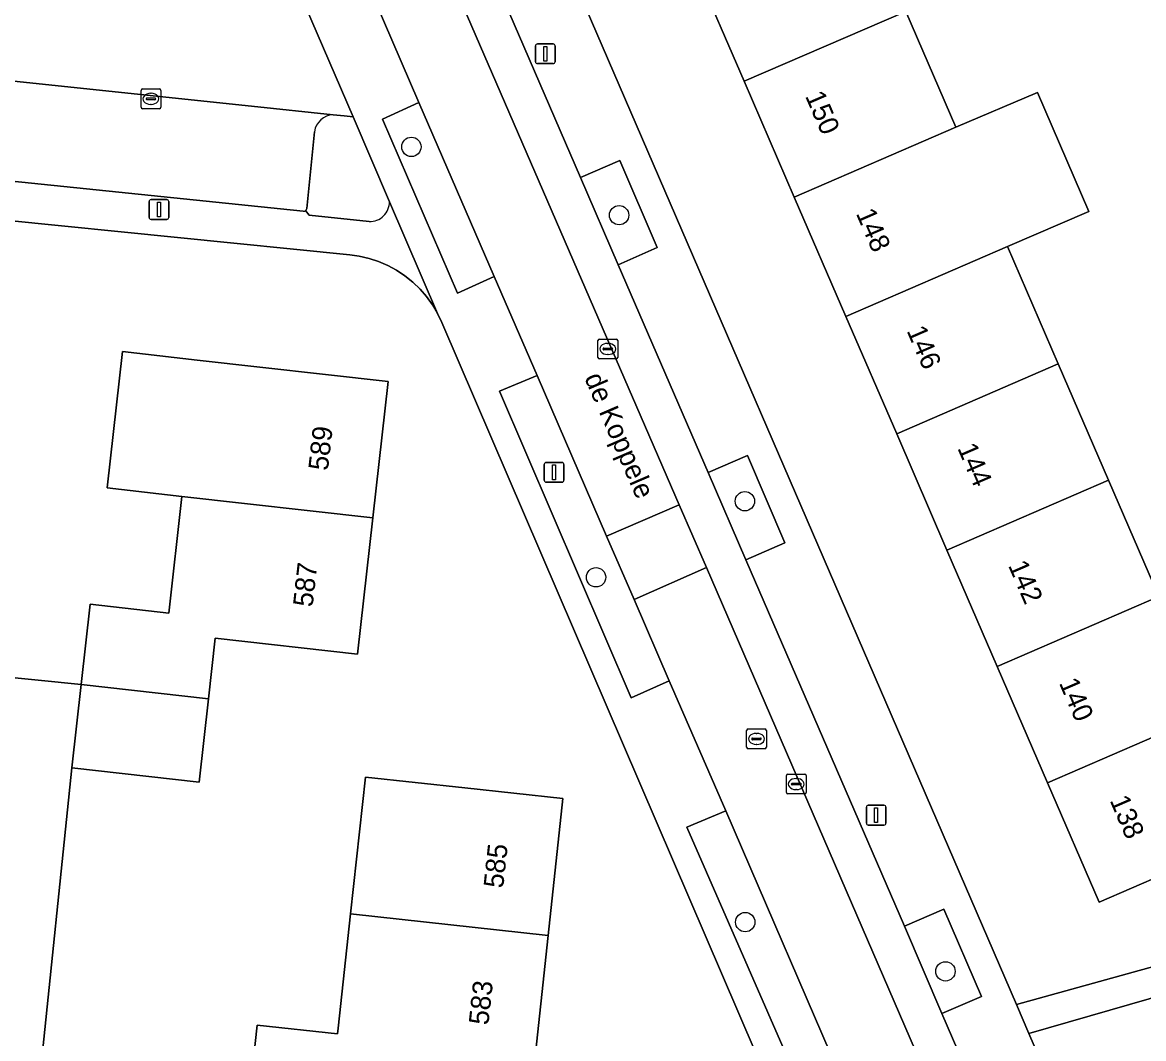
# Model space of a CAD drawing. Extents: x 162026 to 163502, y 387295 to 388169.
# Drawn here: x 162199.2 to 162255.9, y 388022.7 to 388074.1 of the extents above; entities that cross this region are included whole.
import ezdxf

# ---------------------------------------------------------------- set-up
doc = ezdxf.new("R2010")
doc.units = 0
for name, color, linetype in [('IMGEO_Boom', 7, 'Continuous'), ('IMGEO_Erf', 7, 'Continuous'), ('IMGEO_Groenvoorziening', 7, 'Continuous'), ('IMGEO_Kolk', 7, 'Continuous'), ('IMGEO_Lichtmast', 7, 'Continuous'), ('IMGEO_Openbare_ruimte_label', 7, 'Continuous'), ('IMGEO_Pand', 7, 'Continuous'), ('IMGEO_Pand_nummerreeks', 7, 'Continuous'), ('IMGEO_Parkeervlak_open', 7, 'Continuous'), ('IMGEO_Rijbaan_lokaal_open', 7, 'Continuous'), ('IMGEO_Rioolput', 7, 'Continuous'), ('IMGEO_Voetpad_open', 7, 'Continuous')]:
    doc.layers.add(name, color=color, linetype=linetype)

msp = doc.modelspace()

# ---------------------------------------------------------------- linework, layer by layer
at = {"layer": 'IMGEO_Boom'}
for centre in [(162218.858, 388067.822), (162229.36, 388064.369), (162235.718, 388049.909), (162228.193, 388046.062), (162235.737, 388028.632), (162245.86, 388026.143)]:
    msp.add_circle(centre, 0.489, dxfattribs=at)
at = {"layer": 'IMGEO_Erf'}
for points in [[(162261.522, 388091.098), (162242.55, 388093.234), (162223.34, 388084.876), (162249.447, 388024.462), (162267.947, 388029.586)], [(162261.797, 388033.179), (162253.631, 388029.647), (162251.023, 388035.676), (162248.479, 388041.559), (162245.934, 388047.442), (162243.393, 388053.317), (162240.825, 388059.254), (162238.217, 388065.284), (162235.684, 388071.141), (162233.135, 388077.032)], [(162243.851, 388074.671), (162246.384, 388068.815), (162250.512, 388070.57), (162253.108, 388064.563), (162248.992, 388062.784), (162251.561, 388056.846), (162254.101, 388050.972), (162256.646, 388045.089)], [(162240.422, 388012.373), (162220.404, 388058.948), (162220.184, 388059.405), (162219.924, 388059.841), (162219.627, 388060.251), (162219.294, 388060.634), (162218.928, 388060.985), (162218.532, 388061.302), (162218.109, 388061.583), (162217.663, 388061.824), (162217.198, 388062.025), (162216.716, 388062.184), (162216.222, 388062.298), (162215.754, 388062.365), (162198.322, 388064.111)], [(162189.1, 388041.95), (162202.158, 388040.642), (162202.615, 388044.705), (162206.59, 388044.258), (162207.253, 388050.154), (162203.476, 388050.579), (162204.252, 388057.472), (162208.028, 388057.047), (162217.681, 388055.961), (162216.906, 388049.068), (162216.131, 388042.174), (162208.945, 388042.982), (162208.601, 388039.919), (162208.126, 388035.699), (162201.684, 388036.423), (162200.063, 388020.584)], [(162210.625, 388019.406), (162211.059, 388023.421), (162215.13, 388022.981), (162215.161, 388023.267), (162215.786, 388029.043), (162216.535, 388035.96), (162221.553, 388035.417), (162226.523, 388034.879), (162225.774, 388027.96), (162225.025, 388021.039)], [(162299.337, 388025.532), (162289.611, 388026.623), (162289.188, 388022.806), (162286.544, 388023.099), (162283.9, 388023.392), (162284.323, 388027.209), (162276.998, 388028.02), (162276.575, 388024.203), (162273.921, 388024.497), (162271.278, 388024.79), (162271.7, 388028.607), (162270.784, 388028.723), (162270.329, 388028.733), (162270.019, 388028.709), (162269.435, 388028.585), (162250.08, 388022.997), (162258.662, 388003.139)]]:
    msp.add_lwpolyline(points, dxfattribs=at)
at = {"layer": 'IMGEO_Groenvoorziening'}
for points in [[(162219.235, 388070.071), (162217.398, 388069.231), (162221.184, 388060.42), (162223.047, 388061.269)], [(162227.416, 388066.277), (162229.312, 388061.864), (162231.285, 388062.729), (162229.402, 388067.141)], [(162225.214, 388056.269), (162223.313, 388055.466), (162229.974, 388039.966), (162231.893, 388040.822), (162230.114, 388044.937), (162228.73, 388048.137)], [(162233.87, 388051.368), (162235.771, 388046.953), (162237.745, 388047.801), (162235.843, 388052.217)], [(162234.759, 388034.257), (162232.785, 388033.424), (162238.987, 388019.237), (162240.871, 388020.067)], [(162245.771, 388029.279), (162243.789, 388028.432), (162245.674, 388024.015), (162247.68, 388024.879)]]:
    msp.add_lwpolyline(points, close=True, dxfattribs=at)
for points in [[(162215.914, 388069.339), (162215.452, 388069.388), (162214.899, 388069.446)], [(162217.745, 388065.052), (162215.914, 388069.339)], [(162213.961, 388068.59), (162213.574, 388064.707)], [(162201.684, 388036.423), (162202.158, 388040.642), (162189.1, 388041.95), (162190.866, 388058.856), (162191.436, 388064.77), (162184.514, 388065.432), (162181.824, 388042.495), (162182.779, 388041.184), (162188.305, 388038.496), (162189.317, 388037.856), (162190.256, 388037.113), (162191.112, 388036.276), (162191.876, 388035.354), (162192.54, 388034.358), (162193.096, 388033.297), (162193.538, 388032.184), (162193.861, 388031.032), (162194.062, 388029.851), (162194.139, 388028.439), (162193.872, 388025.915), (162191.573, 388004.197), (162194.421, 388003.851), (162198.528, 388003.095)], [(162213.51, 388064.608), (162213.682, 388064.369), (162216.721, 388064.056)], [(162208.241, 387999.434), (162208.298, 387999.5), (162208.358, 388000), (162210.192, 388015.409), (162210.625, 388019.406), (162200.063, 388020.584), (162201.684, 388036.423)]]:
    msp.add_lwpolyline(points, dxfattribs=at)
for centre, radius, start, end in [((162214.947, 388068.451), 0.996, 92.7882, 171.9777), ((162213.396, 388064.752), 0.184, 308.4198, 345.8177), ((162216.774, 388065.026), 0.972, 266.893, 1.5187)]:
    msp.add_arc(centre, radius, start, end, dxfattribs=at)
at = {"layer": 'IMGEO_Kolk'}
for p, q in [((162205.188, 388069.825), (162205.188, 388070.677)), ((162205.263, 388070.751), (162206.115, 388070.751)), ((162205.447, 388070.245), (162205.447, 388070.257)), ((162205.49, 388070.294), (162205.888, 388070.294)), ((162205.676, 388070.531), (162205.701, 388070.531)), ((162205.931, 388070.257), (162205.931, 388070.245)), ((162206.189, 388070.677), (162206.189, 388069.825)), ((162206.115, 388069.751), (162205.263, 388069.751)), ((162205.885, 388070.208), (162205.487, 388070.208)), ((162205.699, 388069.971), (162205.674, 388069.971)), ((162228.289, 388057.182), (162228.289, 388058.034)), ((162228.364, 388058.108), (162229.216, 388058.108)), ((162228.777, 388057.888), (162228.802, 388057.888)), ((162229.29, 388058.034), (162229.29, 388057.182)), ((162228.548, 388057.602), (162228.548, 388057.614)), ((162228.986, 388057.565), (162228.588, 388057.565)), ((162228.591, 388057.651), (162228.989, 388057.651)), ((162228.8, 388057.328), (162228.775, 388057.328)), ((162229.032, 388057.614), (162229.032, 388057.602)), ((162229.216, 388057.108), (162228.364, 388057.108)), ((162237.815, 388035.184), (162237.815, 388036.036)), ((162237.89, 388036.11), (162238.742, 388036.11)), ((162238.117, 388035.653), (162238.515, 388035.653)), ((162238.303, 388035.89), (162238.328, 388035.89)), ((162238.816, 388036.036), (162238.816, 388035.184)), ((162238.742, 388035.11), (162237.89, 388035.11)), ((162238.074, 388035.604), (162238.074, 388035.616)), ((162238.512, 388035.567), (162238.114, 388035.567)), ((162238.326, 388035.33), (162238.301, 388035.33)), ((162238.558, 388035.616), (162238.558, 388035.604))]:
    msp.add_line(p, q, dxfattribs=at)
for points in [[(162205.188, 388069.825), (162205.188, 388070.677)], [(162205.263, 388070.751), (162206.115, 388070.751)], [(162206.189, 388070.677), (162206.189, 388069.825)], [(162206.115, 388069.751), (162205.263, 388069.751)], [(162228.289, 388057.182), (162228.289, 388058.034)], [(162228.364, 388058.108), (162229.216, 388058.108)], [(162229.29, 388058.034), (162229.29, 388057.182)], [(162229.216, 388057.108), (162228.364, 388057.108)], [(162237.815, 388035.184), (162237.815, 388036.036)], [(162237.89, 388036.11), (162238.742, 388036.11)], [(162238.816, 388036.036), (162238.816, 388035.184)], [(162238.742, 388035.11), (162237.89, 388035.11)]]:
    msp.add_lwpolyline(points, dxfattribs=at)
for centre, radius, start, end in [((162205.265, 388070.675), 0.0765, 91.552, 178.448), ((162205.265, 388070.675), 0.0765, 91.552, 178.448), ((162205.487, 388070.254), 0.0403, 85.8775, 175.7526), ((162205.484, 388070.244), 0.0366, 178.938, 274.7102), ((162205.888, 388070.251), 0.043, 264.8664, 352.4533), ((162205.892, 388070.256), 0.0386, 1.7309, 96.639), ((162206.113, 388070.675), 0.0765, 1.552, 88.448), ((162206.113, 388070.675), 0.0765, 1.552, 88.448), ((162205.265, 388069.827), 0.0765, 181.552, 268.448), ((162205.265, 388069.827), 0.0765, 181.552, 268.448), ((162206.113, 388069.827), 0.0765, 271.552, 358.448), ((162206.113, 388069.827), 0.0765, 271.552, 358.448), ((162228.366, 388058.032), 0.0765, 91.552, 178.448), ((162228.366, 388058.032), 0.0765, 91.552, 178.448), ((162229.214, 388058.032), 0.0765, 1.552, 88.448), ((162229.214, 388058.032), 0.0765, 1.552, 88.448), ((162228.588, 388057.611), 0.0403, 85.8775, 175.7526), ((162228.585, 388057.601), 0.0366, 178.938, 274.7102), ((162228.989, 388057.608), 0.043, 264.8664, 352.4533), ((162228.993, 388057.613), 0.0386, 1.7309, 96.639), ((162228.366, 388057.184), 0.0765, 181.552, 268.448), ((162228.366, 388057.184), 0.0765, 181.552, 268.448), ((162229.214, 388057.184), 0.0765, 271.552, 358.448), ((162229.214, 388057.184), 0.0765, 271.552, 358.448), ((162237.892, 388036.034), 0.0765, 91.552, 178.448), ((162237.892, 388036.034), 0.0765, 91.552, 178.448), ((162238.114, 388035.613), 0.0403, 85.8775, 175.7526), ((162238.519, 388035.615), 0.0386, 1.7309, 96.639), ((162238.74, 388036.034), 0.0765, 1.552, 88.448), ((162238.74, 388036.034), 0.0765, 1.552, 88.448), ((162237.892, 388035.186), 0.0765, 181.552, 268.448), ((162237.892, 388035.186), 0.0765, 181.552, 268.448), ((162238.111, 388035.603), 0.0366, 178.938, 274.7102), ((162238.515, 388035.61), 0.043, 264.8664, 352.4533), ((162238.74, 388035.186), 0.0765, 271.552, 358.448), ((162238.74, 388035.186), 0.0765, 271.552, 358.448)]:
    msp.add_arc(centre, radius, start, end, dxfattribs=at)
for centre, major_axis, ratio, start_param, end_param in [((162205.675, 388070.251), (-0.387, 0.002), 0.722429, 4.712389, 7.853982), ((162205.7, 388070.251), (-0.39, 0.002), 0.717154, 1.570796, 4.712389), ((162228.776, 388057.608), (-0.387, 0.002), 0.722429, 4.712389, 7.853982), ((162228.801, 388057.608), (-0.39, 0.002), 0.717154, 1.570796, 4.712389), ((162238.302, 388035.61), (-0.387, 0.002), 0.722429, 4.712389, 7.853982), ((162238.327, 388035.61), (-0.39, 0.002), 0.717154, 1.570796, 4.712389)]:
    msp.add_ellipse(centre, major_axis=major_axis, ratio=ratio, start_param=start_param, end_param=end_param, dxfattribs=at)
at = {"layer": 'IMGEO_Lichtmast'}
for p, q in [((162225.133, 388072.129), (162225.133, 388072.929)), ((162225.133, 388072.929), (162225.133, 388072.129)), ((162225.233, 388073.029), (162226.023, 388073.029)), ((162226.023, 388073.029), (162225.233, 388073.029)), ((162226.123, 388072.929), (162226.123, 388072.129)), ((162226.123, 388072.129), (162226.123, 388072.929)), ((162226.023, 388072.029), (162225.233, 388072.029)), ((162225.233, 388072.029), (162226.023, 388072.029)), ((162205.698, 388065.158), (162206.488, 388065.158)), ((162206.488, 388065.158), (162205.698, 388065.158)), ((162205.598, 388064.258), (162205.598, 388065.058)), ((162205.598, 388065.058), (162205.598, 388064.258)), ((162206.588, 388065.058), (162206.588, 388064.258)), ((162206.588, 388064.258), (162206.588, 388065.058)), ((162206.488, 388064.158), (162205.698, 388064.158)), ((162205.698, 388064.158), (162206.488, 388064.158)), ((162225.578, 388050.969), (162225.578, 388051.769)), ((162225.578, 388051.769), (162225.578, 388050.969)), ((162225.678, 388051.869), (162226.468, 388051.869)), ((162226.468, 388051.869), (162225.678, 388051.869)), ((162226.568, 388051.769), (162226.568, 388050.969)), ((162226.568, 388050.969), (162226.568, 388051.769)), ((162226.468, 388050.869), (162225.678, 388050.869)), ((162225.678, 388050.869), (162226.468, 388050.869)), ((162241.96, 388034.538), (162242.75, 388034.538)), ((162242.75, 388034.538), (162241.96, 388034.538)), ((162241.86, 388033.638), (162241.86, 388034.438)), ((162241.86, 388034.438), (162241.86, 388033.638)), ((162242.85, 388034.438), (162242.85, 388033.638)), ((162242.85, 388033.638), (162242.85, 388034.438)), ((162242.75, 388033.538), (162241.96, 388033.538)), ((162241.96, 388033.538), (162242.75, 388033.538))]:
    msp.add_line(p, q, dxfattribs=at)
for points in [[(162225.553, 388072.904), (162225.703, 388072.904), (162225.703, 388072.154), (162225.553, 388072.154), (162225.553, 388072.904)], [(162206.018, 388065.033), (162206.168, 388065.033), (162206.168, 388064.283), (162206.018, 388064.283), (162206.018, 388065.033)], [(162225.998, 388051.744), (162226.148, 388051.744), (162226.148, 388050.994), (162225.998, 388050.994), (162225.998, 388051.744)], [(162242.28, 388034.413), (162242.43, 388034.413), (162242.43, 388033.663), (162242.28, 388033.663), (162242.28, 388034.413)]]:
    msp.add_lwpolyline(points, dxfattribs=at)
for centre, start, end in [((162225.233, 388072.929), 90, 180), ((162225.233, 388072.929), 90, 180), ((162226.023, 388072.929), 0, 90), ((162226.023, 388072.929), 360, 90), ((162225.233, 388072.129), 180, 270), ((162225.233, 388072.129), 180, 270), ((162226.023, 388072.129), 270, 0), ((162226.023, 388072.129), 270, 0), ((162205.698, 388065.058), 90, 180), ((162205.698, 388065.058), 90, 180), ((162206.488, 388065.058), 0, 90), ((162206.488, 388065.058), 360, 90), ((162205.698, 388064.258), 180, 270), ((162205.698, 388064.258), 180, 270), ((162206.488, 388064.258), 270, 0), ((162206.488, 388064.258), 270, 0), ((162225.678, 388051.769), 90, 180), ((162225.678, 388051.769), 90, 180), ((162226.468, 388051.769), 0, 90), ((162226.468, 388051.769), 360, 90), ((162225.678, 388050.969), 180, 270), ((162225.678, 388050.969), 180, 270), ((162226.468, 388050.969), 270, 0), ((162226.468, 388050.969), 270, 0), ((162241.96, 388034.438), 90, 180), ((162241.96, 388034.438), 90, 180), ((162242.75, 388034.438), 0, 90), ((162242.75, 388034.438), 360, 90), ((162241.96, 388033.638), 180, 270), ((162241.96, 388033.638), 180, 270), ((162242.75, 388033.638), 270, 0), ((162242.75, 388033.638), 270, 0)]:
    msp.add_arc(centre, 0.1, start, end, dxfattribs=at)
at = {"layer": 'IMGEO_Pand'}
for points in [[(162233.135, 388077.032), (162235.684, 388071.141), (162243.851, 388074.671), (162241.303, 388080.563)], [(162246.384, 388068.815), (162243.851, 388074.671), (162235.684, 388071.141), (162238.217, 388065.284)], [(162253.108, 388064.563), (162250.512, 388070.57), (162246.384, 388068.815), (162238.217, 388065.284), (162240.825, 388059.254), (162248.992, 388062.784)], [(162240.825, 388059.254), (162243.393, 388053.317), (162251.561, 388056.846), (162248.992, 388062.784)], [(162217.681, 388055.961), (162208.028, 388057.047), (162204.252, 388057.472), (162203.476, 388050.579), (162207.253, 388050.154), (162216.906, 388049.068)], [(162254.101, 388050.972), (162251.561, 388056.846), (162243.393, 388053.317), (162245.934, 388047.442)], [(162245.934, 388047.442), (162248.479, 388041.559), (162256.646, 388045.089), (162254.101, 388050.972)], [(162208.945, 388042.982), (162216.131, 388042.174), (162216.906, 388049.068), (162207.253, 388050.154), (162206.59, 388044.258), (162202.615, 388044.705), (162202.158, 388040.642), (162208.601, 388039.919)], [(162248.479, 388041.559), (162251.023, 388035.676), (162259.19, 388039.206), (162256.646, 388045.089)], [(162208.601, 388039.919), (162202.158, 388040.642), (162201.684, 388036.423), (162208.126, 388035.699)], [(162251.023, 388035.676), (162253.631, 388029.647), (162261.797, 388033.179), (162259.19, 388039.206)], [(162225.774, 388027.96), (162226.523, 388034.879), (162221.553, 388035.417), (162216.535, 388035.96), (162215.786, 388029.043)], [(162225.774, 388027.96), (162215.786, 388029.043), (162215.161, 388023.267), (162215.13, 388022.981), (162211.059, 388023.421), (162210.625, 388019.406), (162217.638, 388018.644), (162217.98, 388021.802), (162225.025, 388021.039)]]:
    msp.add_lwpolyline(points, close=True, dxfattribs=at)
at = {"layer": 'IMGEO_Parkeervlak_open'}
msp.add_lwpolyline([(162233.87, 388051.368), (162229.312, 388061.864), (162227.416, 388066.277), (162222.488, 388077.667), (162220.499, 388082.24), (162219.67, 388084.193), (162217.803, 388083.405), (162232.4, 388049.731), (162233.78, 388046.56), (162247.319, 388015.274), (162256.129, 387994.89), (162257.953, 387995.69), (162255.25, 388001.914), (162253.211, 388006.595), (162245.674, 388024.015), (162243.789, 388028.432), (162235.771, 388046.953)], close=True, dxfattribs=at)
for points in [[(162214.899, 388069.446), (162210.775, 388069.884), (162181.136, 388072.991)], [(162213.574, 388064.707), (162213.961, 388068.59)], [(162181.477, 388067.866), (162213.389, 388064.569)]]:
    msp.add_lwpolyline(points, dxfattribs=at)
for centre, radius, start, end in [((162214.947, 388068.451), 0.996, 92.7882, 171.9777), ((162213.395, 388064.757), 0.188, 268.111, 307.6187), ((162213.396, 388064.752), 0.184, 308.4198, 345.8177)]:
    msp.add_arc(centre, radius, start, end, dxfattribs=at)
at = {"layer": 'IMGEO_Rijbaan_lokaal_open'}
for points in [[(162207.552, 388092.362), (162206.154, 388092.484), (162189.649, 388094.196), (162182.664, 388094.947), (162180.228, 388073.107), (162181.136, 388072.991), (162210.775, 388069.884), (162214.899, 388069.446), (162215.452, 388069.388), (162215.914, 388069.339), (162213.178, 388075.685), (162211.258, 388075.875), (162208.382, 388076.16), (162189.157, 388078.103), (162188.553, 388078.173)], [(162211.27, 388088.45), (162214.772, 388080.44), (162219.235, 388070.071), (162223.047, 388061.269), (162225.214, 388056.269), (162228.73, 388048.137), (162232.4, 388049.731), (162217.803, 388083.405), (162215.698, 388088.259)], [(162247.319, 388015.274), (162233.78, 388046.56), (162230.114, 388044.937), (162231.893, 388040.822), (162234.759, 388034.257), (162240.871, 388020.067), (162243.691, 388013.525), (162250.922, 387996.833)]]:
    msp.add_lwpolyline(points, dxfattribs=at)
msp.add_lwpolyline([(162232.4, 388049.731), (162228.73, 388048.137), (162230.114, 388044.937), (162233.78, 388046.56)], close=True, dxfattribs=at)
at = {"layer": 'IMGEO_Rioolput'}
for p, q in [((162235.805, 388037.469), (162235.805, 388038.321)), ((162235.88, 388038.395), (162236.732, 388038.395)), ((162236.107, 388037.938), (162236.505, 388037.938)), ((162236.293, 388038.175), (162236.318, 388038.175)), ((162236.806, 388038.321), (162236.806, 388037.469)), ((162236.732, 388037.395), (162235.88, 388037.395)), ((162236.064, 388037.889), (162236.064, 388037.901)), ((162236.502, 388037.852), (162236.104, 388037.852)), ((162236.316, 388037.615), (162236.291, 388037.615)), ((162236.548, 388037.901), (162236.548, 388037.889))]:
    msp.add_line(p, q, dxfattribs=at)
for points in [[(162235.805, 388037.469), (162235.805, 388038.321)], [(162235.88, 388038.395), (162236.732, 388038.395)], [(162236.806, 388038.321), (162236.806, 388037.469)], [(162236.732, 388037.395), (162235.88, 388037.395)]]:
    msp.add_lwpolyline(points, dxfattribs=at)
for centre, radius, start, end in [((162235.882, 388038.319), 0.0765, 91.552, 178.448), ((162235.882, 388038.319), 0.0765, 91.552, 178.448), ((162236.104, 388037.898), 0.0403, 85.8775, 175.7526), ((162236.509, 388037.9), 0.0386, 1.7309, 96.639), ((162236.73, 388038.319), 0.0765, 1.552, 88.448), ((162236.73, 388038.319), 0.0765, 1.552, 88.448), ((162235.882, 388037.471), 0.0765, 181.552, 268.448), ((162235.882, 388037.471), 0.0765, 181.552, 268.448), ((162236.101, 388037.888), 0.0366, 178.938, 274.7102), ((162236.505, 388037.895), 0.043, 264.8664, 352.4533), ((162236.73, 388037.471), 0.0765, 271.552, 358.448), ((162236.73, 388037.471), 0.0765, 271.552, 358.448)]:
    msp.add_arc(centre, radius, start, end, dxfattribs=at)
for centre, major_axis, ratio, start_param, end_param in [((162236.292, 388037.895), (-0.387, 0.002), 0.722429, 4.712389, 7.853982), ((162236.317, 388037.895), (-0.39, 0.002), 0.717154, 1.570796, 4.712389)]:
    msp.add_ellipse(centre, major_axis=major_axis, ratio=ratio, start_param=start_param, end_param=end_param, dxfattribs=at)
at = {"layer": 'IMGEO_Voetpad_open'}
for points in [[(162217.462, 388089.253), (162219.67, 388084.193), (162220.499, 388082.24), (162222.439, 388083.094), (162224.263, 388078.942), (162224.434, 388078.544), (162222.488, 388077.667), (162227.416, 388066.277), (162229.402, 388067.141), (162231.285, 388062.729), (162229.312, 388061.864), (162233.87, 388051.368), (162235.843, 388052.217), (162237.745, 388047.801), (162235.771, 388046.953), (162243.789, 388028.432), (162245.771, 388029.279), (162247.68, 388024.879), (162245.674, 388024.015), (162253.211, 388006.595)], [(162207.72, 388088.631), (162207.867, 388087.996), (162208.124, 388087.243), (162208.345, 388086.704), (162208.535, 388086.273), (162211.796, 388078.889), (162213.178, 388075.685), (162215.914, 388069.339), (162217.745, 388065.052), (162220.184, 388059.405), (162220.404, 388058.948), (162240.422, 388012.373), (162247.117, 387996.582)], [(162232.785, 388033.424), (162234.759, 388034.257), (162231.893, 388040.822), (162229.974, 388039.966), (162223.313, 388055.466), (162225.214, 388056.269), (162223.047, 388061.269), (162221.184, 388060.42), (162217.398, 388069.231), (162219.235, 388070.071), (162214.772, 388080.44), (162211.27, 388088.45)], [(162258.662, 388003.139), (162250.08, 388022.997), (162249.447, 388024.462), (162223.34, 388084.876)], [(162213.389, 388064.569), (162181.477, 388067.866)], [(162198.322, 388064.111), (162215.754, 388062.365), (162216.222, 388062.298), (162216.716, 388062.184), (162217.198, 388062.025), (162217.663, 388061.824), (162218.109, 388061.583), (162218.532, 388061.302), (162218.928, 388060.985), (162219.294, 388060.634), (162219.627, 388060.251), (162219.924, 388059.841), (162220.184, 388059.405), (162217.745, 388065.052)], [(162216.721, 388064.056), (162213.682, 388064.369), (162213.51, 388064.608)], [(162248.605, 387997.004), (162241.8, 388012.719), (162243.691, 388013.525), (162240.871, 388020.067), (162238.987, 388019.237), (162232.785, 388033.424)], [(162267.947, 388029.586), (162249.447, 388024.462), (162250.08, 388022.997), (162269.435, 388028.585)]]:
    msp.add_lwpolyline(points, dxfattribs=at)
for centre, radius, start, end in [((162213.395, 388064.757), 0.188, 268.111, 307.6187), ((162216.774, 388065.026), 0.972, 266.893, 1.5187)]:
    msp.add_arc(centre, radius, start, end, dxfattribs=at)

# ---------------------------------------------------------------- texts
at = {"layer": 'IMGEO_Openbare_ruimte_label'}
msp.add_text('de Koppele', height=1, rotation=293.3866, dxfattribs=at).set_placement((162227.586, 388056.153))
at = {"layer": 'IMGEO_Pand_nummerreeks'}
for s, rotation, p in [('150', 293.3901, (162238.752, 388070.395)), ('148', 293.3901, (162241.319, 388064.461)), ('146', 293.3901, (162243.883, 388058.531)), ('589', 83.5831, (162214.635, 388051.425)), ('144', 293.3901, (162246.45, 388052.597)), ('587', 83.5855, (162213.86, 388044.532)), ('142', 293.3901, (162249.016, 388046.666)), ('140', 293.3901, (162251.585, 388040.726)), ('138', 293.3901, (162254.151, 388034.792)), ('585', 83.8225, (162223.495, 388030.32)), ('583', 83.8237, (162222.746, 388023.4))]:
    msp.add_text(s, height=1, rotation=rotation, dxfattribs=at).set_placement(p)

doc.saveas('drawing.dxf')
